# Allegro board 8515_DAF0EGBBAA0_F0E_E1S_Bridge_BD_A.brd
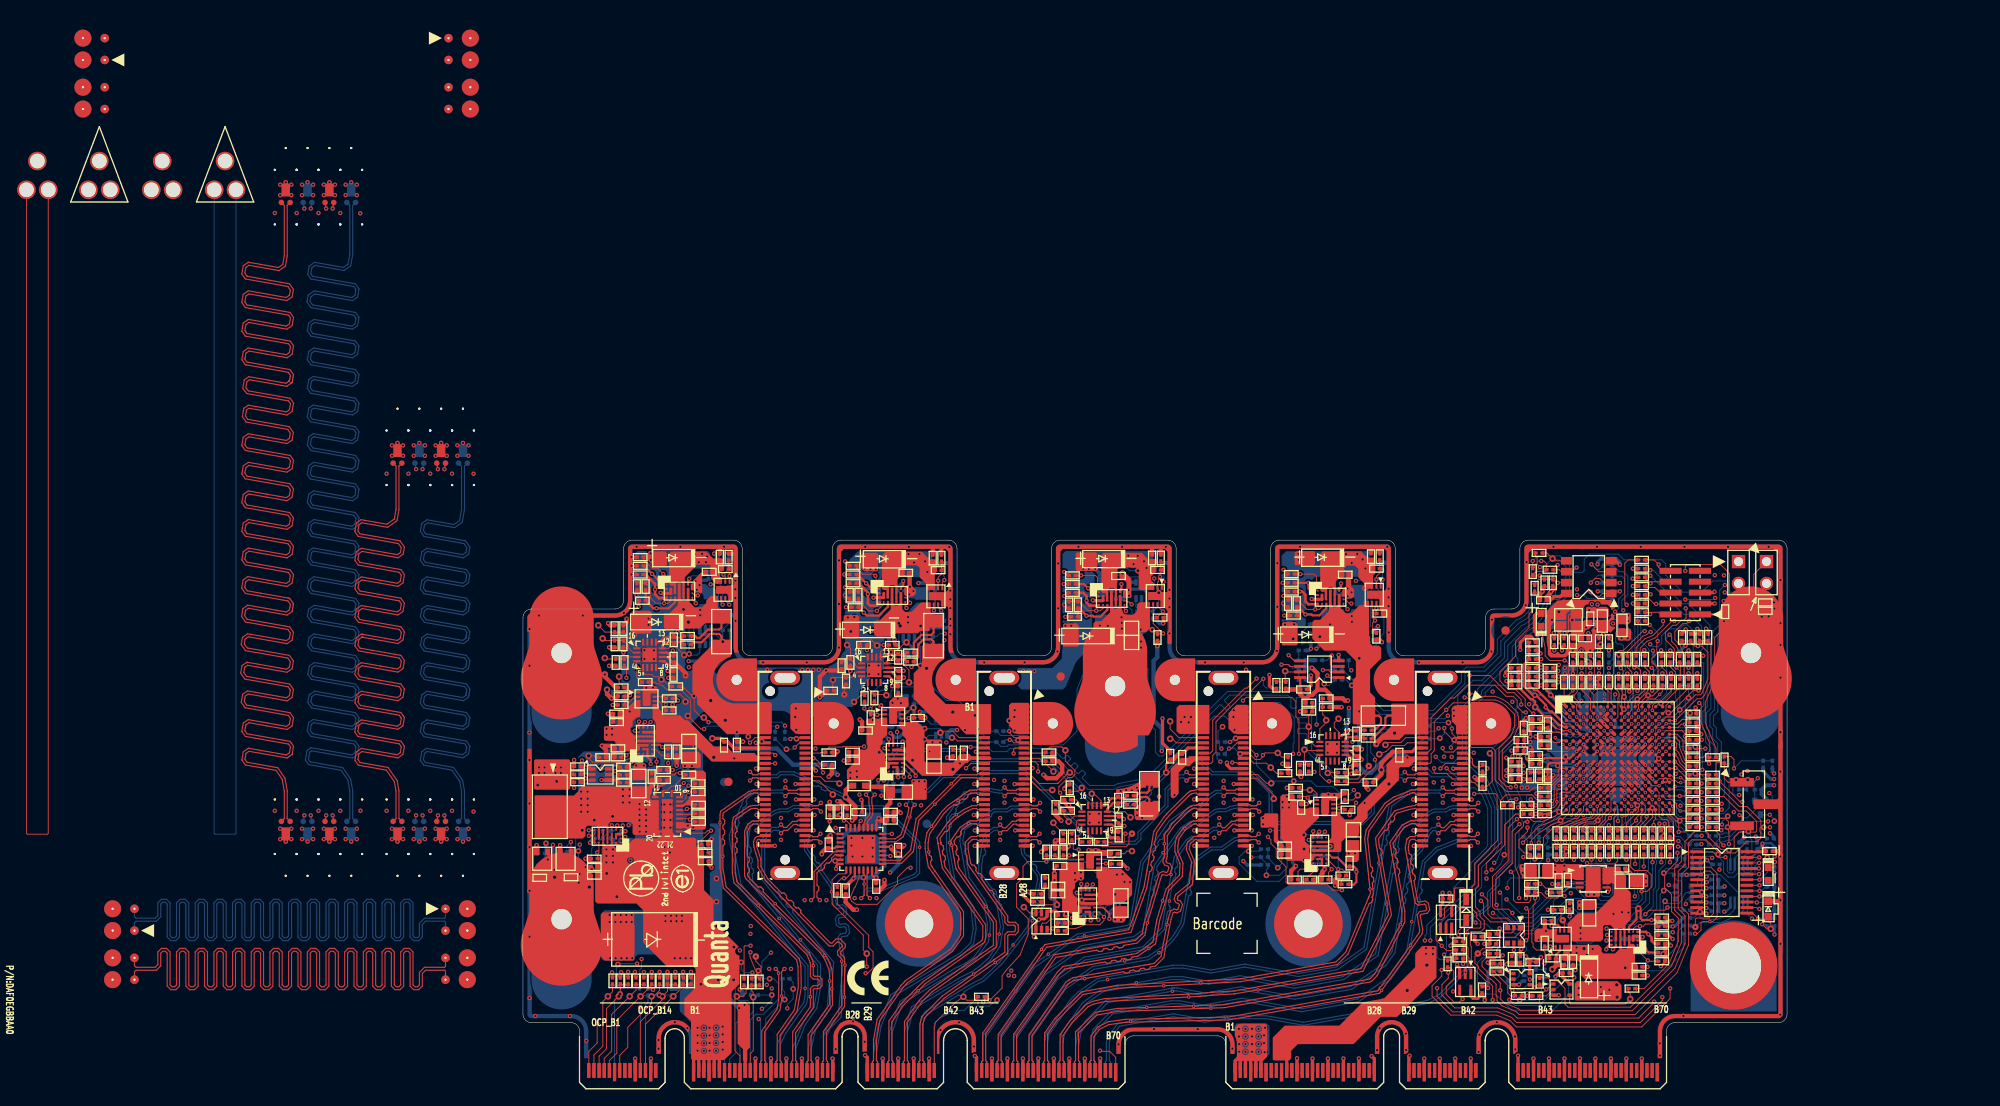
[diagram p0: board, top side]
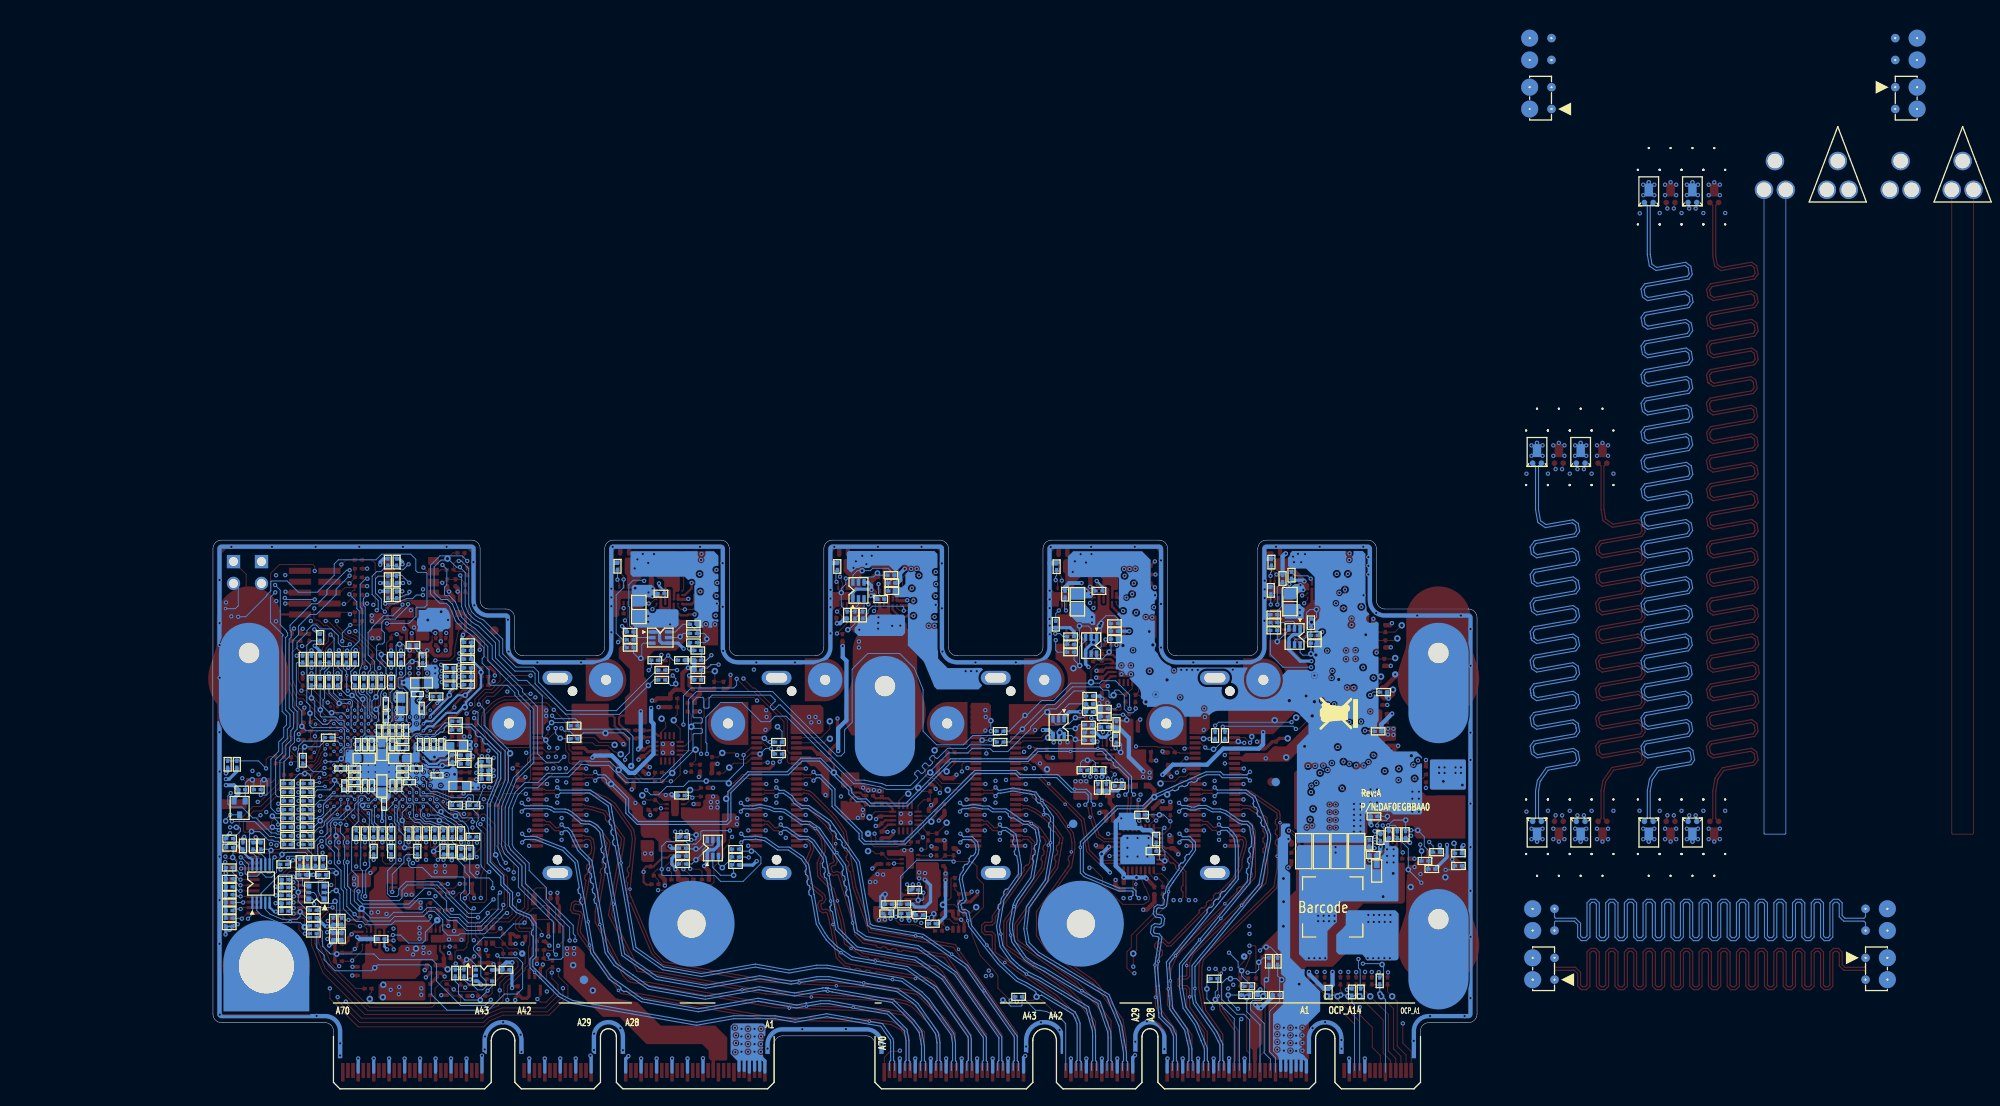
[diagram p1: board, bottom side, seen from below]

Outline 147.1 x 63.9 mm; copper layers: TOP, GND, IN1, GND1, VCC, VCC1, GND2, IN2, GND3, BOTTOM. Coordinates in mm from the lower left corner of the outline.
Outline path: 0,54.88 0,8.71 arc(0.29,8) 1,7.71 5.59,7.71 arc(6.3,7.42) 6.59,6.71 6.59,0.75 7.34,0 15.8,0 16.55,0.75 16.55,5.88 arc(17.68,7) 18.8,5.88 18.8,0.75 19.55,0 36.4,0 37.15,0.75 37.15,6.07 arc(38.08,7) 39,6.07 39,0.75 39.75,0 48.21,0 48.96,0.75 48.96,5.63 arc(50.34,7) 51.71,5.63 51.71,0.75 52.46,0 69.32,0 70.07,0.75 70.07,5.17 arc(70.36,5.88) 71.07,6.17 80.8,6.17 arc(81.51,5.88) 81.8,5.17 81.8,0.75 82.55,0 99.4,0 100.15,0.75 100.15,6.07 arc(101.08,7) 102,6.07 102,0.75 102.75,0 111.21,0 111.96,0.75 111.96,5.63 arc(113.34,7) 114.72,5.63 114.72,0.75 115.47,0 132.32,0 133.07,0.75 133.07,6.71 arc(133.36,7.42) 134.07,7.71 146.1,7.71 arc(146.81,8) 147.1,8.71 147.1,62.9 arc(146.81,63.61) 146.1,63.9 117.01,63.9 arc(116.3,63.61) 116.01,62.9 116.01,56.88 arc(115.72,56.17) 115.01,55.88 113.01,55.88 arc(112.3,55.59) 112.01,54.88 112.01,51.44 arc(111.72,50.73) 111.01,50.44 102.51,50.44 arc(101.8,50.73) 101.51,51.44 101.51,62.9 arc(101.22,63.61) 100.51,63.9 88.01,63.9 arc(87.3,63.61) 87.01,62.9 87.01,51.44 arc(86.72,50.73) 86.01,50.44 77.01,50.44 arc(76.3,50.73) 76.01,51.44 76.01,62.9 arc(75.72,63.61) 75.01,63.9 62.51,63.9 arc(61.8,63.61) 61.51,62.9 61.51,51.44 arc(61.22,50.73) 60.51,50.44 51.51,50.44 arc(50.8,50.73) 50.51,51.44 50.51,62.9 arc(50.22,63.61) 49.51,63.9 37.01,63.9 arc(36.3,63.61) 36.01,62.9 36.01,51.44 arc(35.72,50.73) 35.01,50.44 26.51,50.44 arc(25.8,50.73) 25.51,51.44 25.51,62.9 arc(25.22,63.61) 24.51,63.9 12.71,63.9 arc(12,63.61) 11.71,62.9 11.71,56.88 arc(11.42,56.17) 10.71,55.88 1,55.88 arc(0.29,55.59) 0,54.88

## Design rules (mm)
constraint set DEFAULT: min track width 0.109
net group BIC_ADCVREFN0: nets BIC_ADCVREFN0 BIC_ADCVREFP0
net group BIC_ADCVREFN1: nets BIC_ADCVREFN1 BIC_ADCVREFP1
net group BMC_HARTBEAT_LED: nets BMC_HARTBEAT_LED BMC_HARTBEAT_LED_R
net group CLKBUF_E1S_0_OE_N: nets CLKBUF_E1S_0_OE_N CLKBUF_E1S_0_OE_R_N
net group CLKBUF_E1S_1_OE_N: nets CLKBUF_E1S_1_OE_N CLKBUF_E1S_1_OE_R_N
net group CLKBUF_E1S_2_OE_N: nets CLKBUF_E1S_2_OE_N CLKBUF_E1S_2_OE_R_N
net group CLKBUF_E1S_3_OE_N: nets CLKBUF_E1S_3_OE_N CLKBUF_E1S_3_OE_R_N
net group DELTA_L_85_5INCH_BOT_: nets DELTA_L_85_5INCH_BOT_DN DELTA_L_85_5INCH_BOT_DP
net group DELTA_L_85_5INCH_IN1_: nets DELTA_L_85_5INCH_IN1_DN DELTA_L_85_5INCH_IN1_DP
net group DELTA_L_85_5INCH_IN2_: nets DELTA_L_85_5INCH_IN2_DN DELTA_L_85_5INCH_IN2_DP
net group DELTA_L_85_5INCH_TOP_: nets DELTA_L_85_5INCH_TOP_DN DELTA_L_85_5INCH_TOP_DP
net group DELTA_L_85_10INCH_BOT_: nets DELTA_L_85_10INCH_BOT_DN DELTA_L_85_10INCH_BOT_DP
net group DELTA_L_85_10INCH_IN1_: nets DELTA_L_85_10INCH_IN1_DN DELTA_L_85_10INCH_IN1_DP
net group DELTA_L_85_10INCH_IN2_: nets DELTA_L_85_10INCH_IN2_DN DELTA_L_85_10INCH_IN2_DP
net group DELTA_L_85_10INCH_TOP_: nets DELTA_L_85_10INCH_TOP_DN DELTA_L_85_10INCH_TOP_DP
net group FM_CARD_TYPE: nets CARD_TYPE_R FM_CARD_TYPE
net group FM_CLKBUF_EN: nets FM_CLKBUF_EN FM_CLKBUF_R_EN
net group FM_FRU_WC_N_R: nets FM_FRU_WC_N FM_FRU_WC_N_R
net group FM_MB_SLOT_ID0: nets FM_MB_SLOT_ID0 SLOT_ID0_R
net group FM_MB_SLOT_ID1: nets FM_MB_SLOT_ID1 SLOT_ID1_R
net group FM_P3V3_E1S_0_EN_G: nets FM_P3V3_E1S_0_EN_G FM_P3V3_E1S_0_EN_R_G
net group FM_P3V3_E1S_1_EN_G: nets FM_P3V3_E1S_1_EN_G FM_P3V3_E1S_1_EN_R_G
net group FM_P3V3_E1S_2_EN_G: nets FM_P3V3_E1S_2_EN_G FM_P3V3_E1S_2_EN_R_G
net group FM_P3V3_E1S_3_EN_G: nets FM_P3V3_E1S_3_EN_G FM_P3V3_E1S_3_EN_R_G
net group FM_P12V_E1S_0_EN_G: nets FM_P12V_E1S_0_EN_G FM_P12V_E1S_0_EN_R_G
net group FM_P12V_E1S_1_EN_G: nets FM_P12V_E1S_1_EN_G FM_P12V_E1S_1_EN_R_G
net group FM_P12V_E1S_2_EN_G: nets FM_P12V_E1S_2_EN_G FM_P12V_E1S_2_EN_R_G
net group FM_P12V_E1S_3_EN_G: nets FM_P12V_E1S_3_EN_G FM_P12V_E1S_3_EN_R_G
net group FM_P12V_EDGE_EN: nets FM_P12V_EDGE_EN FM_P12V_EDGE_EN_R
net group FM_P12V_EDGE_EN_G: nets FM_P12V_EDGE_EN_G FM_P12V_EDGE_EN_R_G
net group FM_POWER_EN: nets FM_POWER_EN FM_POWER_EN_R
net group FM_PRSNT_E1S_0_N: nets FM_PRSNT_E1S_0_N FM_PRSNT_E1S_0_R_N
net group FM_PRSNT_E1S_1_N: nets FM_PRSNT_E1S_1_N FM_PRSNT_E1S_1_R_N
net group FM_PRSNT_E1S_2_N: nets FM_PRSNT_E1S_2_N FM_PRSNT_E1S_2_R_N
net group FM_PRSNT_E1S_3_N: nets FM_PRSNT_E1S_3_N FM_PRSNT_E1S_3_R_N
net group FM_PWRDIS_E1S_0: nets FM_PWRDIS_E1S_0 FM_PWRDIS_E1S_R_0
net group FM_PWRDIS_E1S_1: nets FM_PWRDIS_E1S_1 FM_PWRDIS_E1S_R_1
net group FM_PWRDIS_E1S_2: nets FM_PWRDIS_E1S_2 FM_PWRDIS_E1S_R_2
net group FM_PWRDIS_E1S_3: nets FM_PWRDIS_E1S_3 FM_PWRDIS_E1S_R_3
net group IRQ_P3V3_EDGE_FLT_N: nets IRQ_P3V3_EDGE_FLT_N P3V3_EDGE_OCP_FLT_N
net group IRQ_P12V_EDGE_FLT_N: nets IRQ_P12V_EDGE_FLT_N IRQ_P12V_EDGE_FLT_N_R
net group IRQ_SMB_ALERT_N: nets IRQ_SMB_ALERT_N IRQ_SMB_ALERT_R_N
net group IRQ_TMP75_ALERT_N: nets IRQ_TMP75_ALERT_N TMP75_ALERT_N_R
net group JTAG_BIC_DEBUG_R_TDO: nets JTAG_BIC_DEBUG_R_TDO JTAG_BIC_DEBUG_TDO
net group LED_BIC_E1S_0: nets LED_BIC_E1S_0 LED_BIC_E1S_R_0
net group LED_BIC_E1S_1: nets LED_BIC_E1S_1 LED_BIC_E1S_R_1
net group LED_BIC_E1S_2: nets LED_BIC_E1S_2 LED_BIC_E1S_R_2
net group LED_BIC_E1S_3: nets LED_BIC_E1S_3 LED_BIC_E1S_R_3
net group LED_PWRGD_P12V_E1S_ALL: nets LED_PWRGD_P12V_E1S_ALL LED_PWRGD_P12V_E1S_ALL_R
net group P1V2_VDD_PG_R: nets P1V2_VDD_PG_R PWRGD_P1V2_STBY_R
net group P3V3_EDGE_OV: nets P3V3_EDGE_OV P3V3_EDGE_UV
net group P12V_AUX_HSC_PWRGD: nets P12V_AUX_HSC_PWRGD PWRGD_P12V_AUX
net group PU_DB800_HI_BW: nets PU_DB800_HI_BW PU_DB800_HI_BW_R
net group PWRGD_EXP_PWROK: nets PWRGD_EXP_PWROK PWRGD_EXP_PWROK_R
net group RST_BIC_E1S_0_N: nets RST_BIC_E1S_0_N RST_BIC_E1S_0_R_N
net group RST_BIC_E1S_1_N: nets RST_BIC_E1S_1_N RST_BIC_E1S_1_R_N
net group RST_BIC_E1S_2_N: nets RST_BIC_E1S_2_N RST_BIC_E1S_2_R_N
net group RST_BIC_E1S_3_N: nets RST_BIC_E1S_3_N RST_BIC_E1S_3_R_N
net group RST_MB_N: nets RST_MB_N RST_MB_R_N
net group RST_SMB_E1S_0_N: nets RST_SMB_E1S_0_N RST_SMB_E1S_0_R_N
net group RST_SMB_E1S_1_N: nets RST_SMB_E1S_1_N RST_SMB_E1S_1_R_N
net group RST_SMB_E1S_2_N: nets RST_SMB_E1S_2_N RST_SMB_E1S_2_R_N
net group RST_SMB_E1S_3_N: nets RST_SMB_E1S_3_N RST_SMB_E1S_3_R_N
net group SMB_BMC_CPLD_SCL: nets SMB_BMC_CPLD_SCL SMB_BMC_CPLD_SCL_R
net group SMB_BMC_CPLD_SDA: nets SMB_BMC_CPLD_SDA SMB_BMC_CPLD_SDA_R
net group SMB_IPMB_3V3SB_SCL: nets SMB_IPMB_3V3SB_SCL SMB_IPMB_3V3SB_SCL_R
net group SMB_IPMB_3V3SB_SDA: nets SMB_IPMB_3V3SB_SDA SMB_IPMB_3V3SB_SDA_R
net group TDR_DIFF_85_BOT_D: nets TDR_DIFF_85_BOT_DN TDR_DIFF_85_BOT_DP
net group TDR_DIFF_85_IN1_D: nets TDR_DIFF_85_IN1_DN TDR_DIFF_85_IN1_DP
net group TDR_DIFF_85_IN2_D: nets TDR_DIFF_85_IN2_DN TDR_DIFF_85_IN2_DP
net group TDR_DIFF_85_TOP_D: nets TDR_DIFF_85_TOP_DN TDR_DIFF_85_TOP_DP
net group TP_CLK_100M_E1S_0_D: nets TP_CLK_100M_E1S_0_DN TP_CLK_100M_E1S_0_DP
net group TP_CLK_100M_E1S_1_D: nets TP_CLK_100M_E1S_1_DN TP_CLK_100M_E1S_1_DP
net group TP_CLK_100M_E1S_2_D: nets TP_CLK_100M_E1S_2_DN TP_CLK_100M_E1S_2_DP
net group TP_CLK_100M_E1S_3_D: nets TP_CLK_100M_E1S_3_DN TP_CLK_100M_E1S_3_DP
net group BIC_EXTRST_N: nets BIC_EXTRST_N BIC_EXTRST_N_IO_EXP BIC_EXTRST_N_IO_EXP_R BIC_EXTRST_N_R RST_BIC_EXTRST_N
net group BIC_FWSPICK: nets BIC_FWSPICK BIC_FWSPICK_IO_EXP BIC_MB_FWSPICK
net group BIC_SRST_N: nets BIC_SRST_N BIC_SRST_N_IO_EXP BIC_SRST_N_IO_EXP_R BIC_SRST_N_R JTAG_BIC_SRST_N RST_BIC_SRST_N
net group CLK_25M_OSC_BIC_CLKIN: nets CLK_25M_OSC_BIC_CLKIN
net group FM_AUX_PWR_RST_EN: nets FM_AUX_PWR_EN FM_AUX_PWR_EN_R FM_AUX_PWR_RST_EN P1V2_STBY_EN_R
net group IRQ_INA230_E1S_0_ALERT_N: nets INA230_E1S_0_ALERT_R_N IRQ_INA230_E1S_0_ALERT_N IRQ_INA230_E1S_0_ALERT_R_N
net group IRQ_INA230_E1S_1_ALERT_N: nets INA230_E1S_1_ALERT_R_N IRQ_INA230_E1S_1_ALERT_N IRQ_INA230_E1S_1_ALERT_R_N
net group IRQ_INA230_E1S_2_ALERT_N: nets INA230_E1S_2_ALERT_R_N IRQ_INA230_E1S_2_ALERT_N IRQ_INA230_E1S_2_ALERT_R_N
net group IRQ_INA230_E1S_3_ALERT_N: nets INA230_E1S_3_ALERT_R_N IRQ_INA230_E1S_3_ALERT_N IRQ_INA230_E1S_3_ALERT_R_N
net group JTAG_BIC_DEBUG_TCK: nets JTAG_BIC_DEBUG_TCK
net group JTAG_BIC_DEBUG_TDI: nets JTAG_BIC_DEBUG_TDI
net group JTAG_BIC_DEBUG_TMS: nets JTAG_BIC_DEBUG_TMS
net group P1V2_RST_PG_EN: nets P1V2_RST_PG P1V2_RST_PG_EN P1V2_RST_PG_R
net group P3V3_E1S_0_OV: nets FM_P3V3_E1S_0_EN FM_P3V3_E1S_0_EN_D FM_P3V3_E1S_0_R_EN FM_P3V3_E1S_0_SW_EN P3V3_E1S_0_OV
net group P3V3_E1S_1_OV: nets FM_P3V3_E1S_1_EN FM_P3V3_E1S_1_EN_D FM_P3V3_E1S_1_R_EN FM_P3V3_E1S_1_SW_EN P3V3_E1S_1_OV
net group P3V3_E1S_2_OV: nets FM_P3V3_E1S_2_EN FM_P3V3_E1S_2_EN_D FM_P3V3_E1S_2_R_EN FM_P3V3_E1S_2_SW_EN P3V3_E1S_2_OV
net group P3V3_E1S_3_OV: nets FM_P3V3_E1S_3_EN FM_P3V3_E1S_3_EN_D FM_P3V3_E1S_3_R_EN FM_P3V3_E1S_3_SW_EN P3V3_E1S_3_OV
net group P12V_AUX_EN_MP5022: nets FM_P12V_EDGE_EN_D P12V_AUX_EN_MP5022 P12V_AUX_OV P12V_AUX_UV
net group P12V_E1S_0_IN_N: nets P12V_E1S_0_IN_N P12V_E1S_0_IN_P P12V_E1S_0_IN_SENN P12V_E1S_0_IN_SENP
net group P12V_E1S_0_OV: nets FM_P12V_E1S_0_EN FM_P12V_E1S_0_EN_D FM_P12V_E1S_0_R_EN FM_P12V_E1S_0_SW_EN P12V_E1S_0_OV
net group P12V_E1S_1_IN_N: nets P12V_E1S_1_IN_N P12V_E1S_1_IN_P P12V_E1S_1_IN_SENN P12V_E1S_1_IN_SENP
net group P12V_E1S_1_OV: nets FM_P12V_E1S_1_EN FM_P12V_E1S_1_EN_D FM_P12V_E1S_1_R_EN FM_P12V_E1S_1_SW_EN P12V_E1S_1_OV
net group P12V_E1S_2_IN_N: nets P12V_E1S_2_IN_N P12V_E1S_2_IN_P P12V_E1S_2_IN_SENN P12V_E1S_2_IN_SENP
net group P12V_E1S_2_OV: nets FM_P12V_E1S_2_EN FM_P12V_E1S_2_EN_D FM_P12V_E1S_2_R_EN FM_P12V_E1S_2_SW_EN P12V_E1S_2_OV
net group P12V_E1S_3_IN_N: nets P12V_E1S_3_IN_N P12V_E1S_3_IN_P P12V_E1S_3_IN_SENN P12V_E1S_3_IN_SENP
net group P12V_E1S_3_OV: nets FM_P12V_E1S_3_EN FM_P12V_E1S_3_EN_D FM_P12V_E1S_3_R_EN FM_P12V_E1S_3_SW_EN P12V_E1S_3_OV
net group PRSNTB0_N: nets PRSNTA1_N PRSNTB0_N PRSNTB1_N PRSNTB2_N PRSNTB3_N
net group RESET_R_EXTRST_N: nets RESET_R_EXTRST_N RESET_R_N RESET_R_SRST_N SELECT_RST_N SELECT_RST_R_N
net group SMB_CLKBUF_SCL_R: nets SMB_BIC_SENSOR_R_SCL SMB_CLKBUF_SCL_R SMB_FRU_SCL_R SMB_SENSOR_SCL SMB_TMP75_SCL_R
net group SMB_E1S_0_SDA: nets SMB_BIC_E1S_0_R_SDA SMB_E1S_0_R_SDA SMB_E1S_0_SDA SMB_INA230_E1S_0_SDA
net group SMB_E1S_1_SDA: nets SMB_BIC_E1S_1_R_SDA SMB_E1S_1_R_SDA SMB_E1S_1_SDA SMB_INA230_E1S_1_SDA
net group SMB_E1S_2_SDA: nets SMB_BIC_E1S_2_R_SDA SMB_E1S_2_R_SDA SMB_E1S_2_SDA SMB_INA230_E1S_2_SDA
net group SMB_E1S_3_SDA: nets SMB_BIC_E1S_3_R_SDA SMB_E1S_3_R_SDA SMB_E1S_3_SDA SMB_INA230_E1S_3_SDA
net group SMB_INA230_E1S_0_SCL: nets SMB_BIC_E1S_0_R_SCL SMB_E1S_0_R_SCL SMB_E1S_0_SCL SMB_INA230_E1S_0_SCL
net group SMB_INA230_E1S_1_SCL: nets SMB_BIC_E1S_1_R_SCL SMB_E1S_1_R_SCL SMB_E1S_1_SCL SMB_INA230_E1S_1_SCL
net group SMB_INA230_E1S_2_SCL: nets SMB_BIC_E1S_2_R_SCL SMB_E1S_2_R_SCL SMB_E1S_2_SCL SMB_INA230_E1S_2_SCL
net group SMB_INA230_E1S_3_SCL: nets SMB_BIC_E1S_3_R_SCL SMB_E1S_3_R_SCL SMB_E1S_3_SCL SMB_INA230_E1S_3_SCL
net group SMB_IO_EXP_SCL: nets SMB_IO_EXP_SCL SMB_MB_CPLD_BIC_SCL SMB_MB_CPLD_SCL SMB_MB_CPLD_SCL_R
net group SMB_IO_EXP_SDA: nets SMB_IO_EXP_SDA SMB_MB_CPLD_BIC_SDA SMB_MB_CPLD_SDA SMB_MB_CPLD_SDA_R
net group SMB_IPMB_3V3AUX_SCL: nets SMB_IPMB_3V3AUX_SCL SMB_IPMB_AUX_SCL_R SMB_MBBIC_BIC_R_SCL
net group SMB_IPMB_3V3AUX_SDA: nets SMB_IPMB_3V3AUX_SDA SMB_IPMB_AUX_SDA_R SMB_MBBIC_BIC_R_SDA
net group SMB_SENSOR_SDA: nets SMB_BIC_SENSOR_R_SDA SMB_CLKBUF_SDA_R SMB_FRU_SDA_R SMB_SENSOR_SDA SMB_TMP75_SDA_R
net group UART_BIC5_R_RXD: nets UART_BIC5_R_RXD UART_HOST_TXD UART_MB_TX UART_MB_TX_R
net group UART_BIC5_R_TXD: nets UART_BIC5_R_TXD UART_HOST_RXD UART_MB_RX

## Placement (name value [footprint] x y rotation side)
C48  0.047UF  [C0402-0201]  23.93 61.34 90 bottom
C49  0.047UF  [C0402-0201]  48.92 60.81 90 bottom
C50  0.1UF  [C0402-0201]  22.91 61.93 90 top
C51  10UF  [C0805_H61]  21.77 56.74 90 bottom
C52  0.1UF  [C0402-0201]  47.68 61.8 90 top
C53  10UF  [C0805_H61]  46.5 56.73 90 bottom
C54  0.047UF  [C0402-0201]  74.45 60.83 90 bottom
C55  0.047UF  [C0402-0201]  100.03 60.86 90 bottom
C56  0.1UF  [C0402-0201]  73.2 61.82 90 top
C57  10UF  [C0805_H61]  70.82 52.81 270 top
C58  0.1UF  [C0402-0201]  98.68 61.98 90 top
C59  10UF  [C0805_H61]  97.54 55.83 90 bottom
C60  100NF  [C0402-0201]  11.43 46.74 180 top
C61  100NF  [C0402-0201]  43.36 44.25 0 bottom
C62  0.1UF  [C0402-0201]  10.9 43.69 180 top
C63  0.1UF  [C0402-0201]  39.86 41.73 180 top
C64  10UF  [C0805_H61]  19.3 39.62 270 top
C65  10UF  [C0805_H61]  47.83 38.4 90 top
C66  100NF  [C0402-0201]  89.92 35.05 180 top
C67  100NF  [C0402-0201]  62.89 27.58 90 top
C68  0.1UF  [C0402-0201]  90.55 32.77 90 top
C69  0.1UF  [C0402-0201]  62.5 25.95 180 top
C70  10UF  [C0805_H61]  96.65 29.34 270 top
C71  10UF  [C0805_H61]  69.57 21.64 270 top
C72  0.1UF  [C0402-0201]  17.53 48.26 270 top
C73  0.1UF  [C0402-0201]  17.53 50.04 270 top
C74  0.1UF  [C0402-0201]  17.55 52.3 270 top
C75  0.1UF  [C0402-0201]  43.66 46.51 270 top
C76  0.1UF  [C0402-0201]  43.66 48.29 270 top
C77  0.1UF  [C0402-0201]  43.66 50.27 270 top
C78  0.1UF  [C0402-0201]  69.32 29.54 270 top
C79  0.1UF  [C0402-0201]  69.32 31.32 270 top
C80  0.1UF  [C0402-0201]  69.27 33.6 270 top
C81  0.1UF  [C0402-0201]  97 37.36 270 top
C82  0.1UF  [C0402-0201]  97 39.14 270 top
C83  0.1UF  [C0402-0201]  96.98 41.33 270 top
C84  0.1UF  [C0402-0201]  118.75 56.9 0 top
C85  0.1UF  [C0402-0201]  90.83 46.51 0 top
C86  0.1UF  [C0402-0201]  122.2 14.81 90 top
C87  0.1UF  [C0402-0201]  118.9 16.97 270 top
C88  10UF  [C0805_H57]  124.08 20.5 90 top
C89  1000PF  [C0402-0201]  133.12 17.75 270 bottom
C90  1000PF  [C0402-0201]  132.11 17.75 270 bottom
C91  1000PF  [C0402-0201]  111.15 17.73 180 top
C92  1000PF  [C0402-0201]  116.07 15.07 90 top
C96  1UF  [C0402-0201]  13.64 59.89 0 top
C102  1UF  [C0402-0201]  38.4 58.88 0 top
C105  1UF  [C0402-0201]  63.93 57.76 0 top
C108  1UF  [C0402-0201]  89.41 57.91 0 top
C109  4700PF  [C0402-0201]  21.59 59.82 270 bottom
C110  4700PF  [C0402-0201]  43.99 57.99 0 bottom
C111  4700PF  [C0402-0201]  69.39 57.02 0 bottom
C112  4700PF  [C0402-0201]  94.97 57.66 0 bottom
C113  1UF  [C0402-0201]  11.06 39.65 0 top
C115  0.01UF  [C0402-0201]  11.51 41.63 180 bottom
C116  1UF  [C0402-0201]  38.35 38.23 0 top
C118  0.01UF  [C0402-0201]  41.99 40.72 90 bottom
C119  1UF  [C0402-0201]  62.26 22.66 0 top
C121  0.01UF  [C0402-0201]  65.43 23.16 0 bottom
C122  1UF  [C0402-0201]  88.64 27.27 0 top
C124  0.01UF  [C0402-0201]  92.43 29.31 0 bottom
C125  1UF  [C0402-0201]  129.86 14.21 180 top
C127  0.01UF  [C0402-0201]  127.53 17.45 0 bottom
C128  1UF  [C0402-0201]  16.36 37.13 180 top
C129  1UF  [C0402-0201]  44.12 35.1 90 bottom
C130  1UF  [C0402-0201]  66.6 20.42 0 bottom
C131  1UF  [C0402-0201]  93.34 24.36 0 top
C132  1UF  [C0402-0201]  132.51 16.89 180 top
C147  10UF  [C0402-0201]  42.77 32.25 0 top
C148  0.1UF  [C0402-0201]  42.77 31.24 0 top
C149  0.1UF  [C0402-0201]  37.56 23.06 270 top
C150  0.1UF  [C0402-0201]  41.11 23.57 270 top
C157  10UF  [C0402-0201]  39.08 32.23 0 top
C158  0.1UF  [C0402-0201]  43.64 27.79 90 top
C159  0.1UF  [C0402-0201]  35.57 28.42 90 top
C160  1UF  [C0402-0201]  21.67 60.21 180 top
C161  1UF  [C0402-0201]  44.54 60.09 0 top
C162  1UF  [C0402-0201]  69.3 59.73 0 top
C163  1UF  [C0402-0201]  95.68 59.88 0 top
C164  1UF  [C0402-0201]  10.89 42.71 0 top
C165  1UF  [C0402-0201]  38.35 39.26 0 top
C166  1UF  [C0402-0201]  62.26 23.65 0 top
C167  1UF  [C0402-0201]  88.64 28.32 0 top
C168  1UF  [C0402-0201]  129.87 13.19 180 top
C169  1UF  [C0402-0201]  8.3 25.83 180 top
C170  1UF  [C0402-0201]  11.99 31.73 180 bottom
C171  4700PF  [C0402-0201]  8.29 26.8 180 top
C172  10UF  [C0805_H61]  13.46 35.56 90 top
C176  1UF  [C0402-0201]  21.21 26.52 0 top
C177  0.047UF  [C0402-0201]  20.44 33.08 0 top
C178  0.01UF  [C0402-0201]  20.39 35.58 180 top
C179  0.22UF  [C0402-0201]  20.44 31.1 180 top
C180  1UF  [C0402-0201]  12.1 27.23 0 bottom
C202  0.01UF  [C0402-0201]  117.86 43.05 180 top
C203  0.01UF  [C0402-0201]  119.25 42.42 270 top
C204  0.01UF  [C0402-0201]  117.86 42.04 180 top
C205  0.01UF  [C0402-0201]  117.86 37.85 180 bottom
C206  0.01UF  [C0402-0201]  119.25 38.48 90 bottom
C207  0.01UF  [C0402-0201]  117.86 38.86 180 bottom
C208  0.1UF  [C0402_OCTAGONXA]  129.43 40.09 270 bottom
C209  0.22UF  [C0402_OCTAGONXA]  125 39.7 0 bottom
C210  0.1UF  [C0402_OCTAGONXA]  126.21 41.7 90 bottom
C211  0.1UF  [C0402_OCTAGONXA]  125.41 35.31 90 bottom
C212  0.1UF  [C0402_OCTAGONXA]  130.63 35.71 180 bottom
C213  0.1UF  [C0402_OCTAGONXA]  127.02 41.7 90 bottom
C214  0.1UF  [C0402_OCTAGONXA]  126.21 35.31 90 bottom
C215  0.1UF  [C0402_OCTAGONXA]  127.79 41.7 90 bottom
C216  1UF  [C0402_OCTAGONXA]  125.03 36.51 0 bottom
C217  1UF  [C0402_OCTAGONXA]  130.63 36.51 180 bottom
C218  1UF  [C0402_OCTAGONXA]  131.81 35.3 270 bottom
C219  22UF  [C0603]  125.36 38.47 0 bottom
C220  0.1UF  [C0402_OCTAGONXA]  125.02 40.5 0 bottom
C221  0.1UF  [C0402_OCTAGONXA]  126.23 40.09 270 bottom
C222  0.1UF  [C0402_OCTAGONXA]  128.63 40.09 270 bottom
C223  1UF  [C0402_OCTAGONXA]  128.61 35.31 90 bottom
C224  1UF  [C0402_OCTAGONXA]  130.63 37.31 180 bottom
C225  22UF  [C0603]  127.44 35.27 90 bottom
C226  22UF  [C0603]  127.44 39.54 270 bottom
C227  22UF  [C0603]  129.5 38.47 180 bottom
C228  0.1UF  [C0402_OCTAGONXA]  122.22 40.1 90 bottom
C229  1UF  [C0402_OCTAGONXA]  121.42 40.1 90 bottom
C230  1UF  [C0402_OCTAGONXA]  120.52 40.1 90 bottom
C231  1UF  [C0402_OCTAGONXA]  123.02 40.1 90 bottom
C232  1UF  [C0402_OCTAGONXA]  126.99 43.31 270 bottom
C233  0.1UF  [C0402_OCTAGONXA]  129.4 35.31 90 bottom
C234  1UF  [C0402_OCTAGONXA]  130.23 40.09 270 bottom
C235  2.2UF  [C0402-0201]  123.83 51.69 0 bottom
C236  0.1UF  [C0402-0201]  122.17 52.07 270 top
C237  22UF  [C0603]  125.6 54.48 270 top
C239  1UF  [C0402_OCTAGONXA]  125.03 37.31 0 bottom
C240  0.1UF  [C0402_OCTAGONXA]  123.43 37.31 180 bottom
C243  0.1UF  [C0402_OCTAGONXA]  122.81 44.32 90 bottom
C244  4.7UF  [C0402_OCTAGONXA]  123.32 45.97 180 bottom
C246  0.1UF  [C0402_OCTAGONXA]  125.41 41.7 90 bottom
C247  4.7UF  [C0402_OCTAGONXA]  124.62 41.7 90 bottom
C249  22UF  [C0805_H61]  118.24 25.4 180 top
C250  0.1UF  [C0402-0201]  120.52 24.26 270 top
C251  10UF  [C0805_H61]  128.75 24.17 0 top
C252  0.001UF  [C0402]  117.35 22.86 180 top
C284  0.1UF  [C0402-0201]  115.44 46.99 0 top
C285  0.1UF  [C0402-0201]  117.47 50.04 180 top
C286  0.1UF  [C0402-0201]  117.47 50.04 180 bottom
C287  0.1UF  [C0402-0201]  119.25 36.45 90 top
C288  0.1UF  [C0402-0201]  115.44 36.07 0 bottom
C289  0.1UF  [C0402-0201]  115.44 36.07 0 top
C290  0.1UF  [C0402-0201]  116.08 39.4 0 top
C291  0.1UF  [C0402-0201]  119.51 46.99 180 top
C292  0.1UF  [C0402-0201]  117.47 47.07 180 top
C293  0.1UF  [C0402-0201]  117.47 47.07 180 bottom
C294  0.1UF  [C0402-0201]  119.51 46.99 180 bottom
C295  0.1UF  [C0402-0201]  143.61 28.29 90 bottom
C296  0.1UF  [C0402-0201]  117.86 37.85 0 top
C297  0.1UF  [C0402_OCTAGONXA]  132.23 37.31 0 bottom
C298  0.1UF  [C0402_OCTAGONXA]  130.63 34.91 180 bottom
C299  0.1UF  [C0402-0201]  139.91 55.57 90 top
C300  0.1UF  [C0402_OCTAGONXA]  126.98 44.88 90 bottom
C301  0.1UF  [C0402_OCTAGONXA]  127.18 33.13 270 bottom
C302  0.1UF  [C0402-0201]  4.7 27.56 180 bottom
C303  0.1UF  [C0402-0201]  2.16 27.43 180 bottom
C304  0.1UF  [C0402-0201]  143.74 34.84 0 bottom
C306  0.1UF  [C0402-0201]  117.5 14.73 0 top
C307  0.1UF  [C0402-0201]  121.39 13.49 0 top
C308  0.1UF  [C0402-0201]  107.42 22.15 0 top
C309  0.1UF  [C0402-0201]  113 13.87 180 bottom
C310  1UF  [C0402-0201]  108.99 17.17 0 top
C311  0.1UF  [C0402-0201]  111.61 11.53 90 top
C312  0.1UF  [C0402_OCTAGONXA]  121.03 36.51 180 bottom
C313  0.1UF  [C0402_OCTAGONXA]  124.23 35.71 0 bottom
C314  0.1UF  [C0402-0201]  145.04 27.68 0 top
C315  0.1UF  [C0402-0201]  18.92 52.81 180 bottom
C316  0.1UF  [C0402-0201]  42.19 53.29 180 bottom
C317  0.1UF  [C0402-0201]  68.1 58.9 180 bottom
C318  0.1UF  [C0402-0201]  91.19 51.97 0 bottom
C319  0.1UF  [C0402-0201]  11.68 35.66 180 top
C320  0.1UF  [C0402-0201]  45.21 41.49 180 bottom
C321  0.1UF  [C0402-0201]  59.87 21.79 180 top
C322  0.1UF  [C0402-0201]  92.46 27.1 0 bottom
D2  SMF14A  [SOD123F]  17.35 61.8 0 top
D3  SMF14A  [SOD123F]  41.86 61.67 0 top
D4  SS1040  [SOD123_2-65X1-6]  15.37 54.36 0 top
D5  SS1040  [SOD123_2-65X1-6]  40.03 53.44 0 top
D6  SMF14A  [SOD123F]  67.39 61.7 0 top
D7  SMF14A  [SOD123F]  92.86 61.85 0 top
D8  SS1040  [SOD123_2-65X1-6]  65.56 52.73 0 top
D9  SS1040  [SOD123_2-65X1-6]  91.03 52.88 0 top
D10  LED BLUE  [LED_LTSTS270KSKT]  144.91 20.95 90 top
D11  LED_GREEN  [LED_19217_H22]  144.91 25.02 90 top
D21  SMF14A  [SOD123F]  124.05 12.85 90 top
D22  SBR15U30SP5-13  [POWERDI5XA]  3.13 32.84 270 top
D23  SMCJ13A-13-F-01  [D_SMCJ170]  15.11 17.4 0 top
D24  LED_GREEN  [LED_19217_H22]  118.49 54.61 270 top
D25  SDMK0340L-7-F  [SOD323XB]  109.75 20.85 90 top
DM4  -  [PB-E1_SMALL]  13.76 24.5 90 top
DM5  -  [WEEE]  13.84 42.04 90 bottom
DM6  CE_LOGO_4.8X4  [CE_5X4]  37.71 10.88 0 top
GF1  FCONN168_6-2340321-2  [GOLD_168P_6-2340321-2]  38.06 6.08 0 top
GF2  FCONN140_6-2340324-2  [GOLD_140P_6-2340324-2]  101.08 6.08 0 top
H3  -  [HOLE_C10-2D6-4B10_R5-6X10B_NPB]  140.88 14.31 0 top
H4  -  [HOLE_C7-5D3_5B7_OB7XC4-75TC3-5B_NPM_SPD]  4.49 50.76 0 top
H5  -  [HOLE_C8D3-3B10_NPM]  91.4 19.23 0 top
H6  -  [HOLE_C5D2B4_R2-23X5T_NPM]  24.86 47.63 90 top
H7  -  [HOLE_C7-5D3_5B7_OB7XC4-75TC3-5B_NPM_SPD]  4.49 19.76 0 top
H8  -  [HOLE_C7-5D3_5B7_OB7XC4-75TC3-5B_NPM_SPD]  68.9 46.9 0 top
H9  -  [HOLE_C7-5D3_5B7_OB7XC4-75TC3-5B_NPM_SPD]  142.9 50.76 0 top
H10  -  [HOLE_C8D3-3B10_NPM]  46.1 19.23 0 top
H11  -  [HOLE_C5D2B4_R2-23X5T_NPM]  36.16 42.55 270 top
H12  -  [HOLE_C5D2B4_R2-23X5T_NPM]  50.36 47.63 90 top
H13  -  [HOLE_C5D2B4_R2-23X5T_NPM]  61.66 42.55 270 top
H14  -  [HOLE_C5D2B4_R2-23X5T_NPM]  75.86 47.63 90 top
H15  -  [HOLE_C5D2B4_R2-23X5T_NPM]  87.16 42.55 270 top
H16  -  [HOLE_C5D2B4_R2-23X5T_NPM]  101.36 47.63 90 top
H17  -  [HOLE_C5D2B4_R2-23X5T_NPM]  112.66 42.55 270 top
J1  SCONN3_212-H91-03GBR1  [HEADER1X3SXE_H367]  143.23 33.16 0 top
J2  SCONN10_232-H97-05GBR1  [HEADER2X5SXM]  135.25 57.78 180 top
J4  SCONN56_1-2327679-3  [CON_F56S2H4D_P0-6W4-6_LUHXA]  30.51 36.5 0 top
J5  SCONN56_1-2327679-3  [CON_F56S2H4D_P0-6W4-6_LUHXA]  56.01 36.5 0 top
J6  SCONN56_1-2327679-3  [CON_F56S2H4D_P0-6W4-6_LUHXA]  81.51 36.5 0 top
J7  SCONN56_1-2327679-3  [CON_F56S2H4D_P0-6W4-6_LUHXA]  107.01 36.5 0 top
J8  DELTA-L  [TRIANG_LAUNCH_3PXA]  -14.6 29.84 0 top
J9  DELTA-L  [TRIANG_LAUNCH_3PXA]  -14.61 74.17 180 top
J10  DELTA-L  [TRIANG_LAUNCH_3PXA]  -6.99 29.84 180 bottom
J11  DELTA-L  [TRIANG_LAUNCH_3PXA]  -6.98 74.17 0 bottom
J12  -  [TDR_3P_C85P67_141_100M_Q]  -41.98 108.05 0 bottom
J13  DELTA-L  [TRIANG_LAUNCH_3PXA]  -12.06 29.84 180 bottom
J14  DELTA-L  [TRIANG_LAUNCH_3PXA]  -12.06 74.17 0 bottom
J15  -  [TDR_3P_C85P67_141_100M_Q]  -34.66 108.05 180 top
J16  -  [TDR_3P_C85P67_141_100M_Q]  -49.3 108.05 180 top
J17  DELTA-L  [TRIANG_LAUNCH_3PXA]  -9.53 74.17 180 top
J18  DELTA-L  [TRIANG_LAUNCH_3PXA]  -9.52 29.84 0 top
J19  DELTA-L  [TRIANG_LAUNCH_3PXA]  -27.61 104.52 180 top
J20  DELTA-L  [TRIANG_LAUNCH_3PXA]  -27.6 29.84 0 top
J21  DELTA-L  [TRIANG_LAUNCH_3PXA]  -19.98 104.52 0 bottom
J22  DELTA-L  [TRIANG_LAUNCH_3PXA]  -19.99 29.84 180 bottom
J23  DELTA-L  [TRIANG_LAUNCH_3PXA]  -25.07 29.84 180 bottom
J24  DELTA-L  [TRIANG_LAUNCH_3PXA]  -25.06 104.52 0 bottom
J25  DELTA-L  [TRIANG_LAUNCH_3PXA]  -22.52 29.84 0 top
J26  DELTA-L  [TRIANG_LAUNCH_3PXA]  -22.53 104.52 180 top
J27  -  [TDR_3P_C85P67_141_100M_Q]  -56.51 108.05 0 bottom
J29  CONN2_210-HP1-02GBR05K  [HEADER1X2XJ_H339]  144.71 61.4 0 top
J30  CONN2_210-HP1-02GBR05K  [HEADER1X2XJ_H339]  141.45 61.4 0 top
L4  HCB2012KF-331T30  [L0805]  43.69 34.54 180 top
L5  BLM18PG121SN1D  [L0603]  118.75 40.01 180 bottom
L6  BLM15PX121SN1D  [L0402]  123.57 52.45 180 top
L7  BLM18KG121TN1D  [L0603]  118.36 35.2 180 bottom
L8  BLM18KG121TN1D  [L0603]  122.83 47.27 180 bottom
L9  BLM18KG121TN1D  [L0603]  125.1 44.85 90 bottom
ME1  -  [PCB_VENDOR_LOGO_15X8]  75.28 14.36 0 top
NOREF  -  []  115.8 1.94 0 top
NOREF#2  -  []  89.47 43.52 0 top
NOREF#3  -  []  24.86 47.63 0 top
NOREF#4  -  []  25.1 48.6 0 top
NOREF#5  -  []  78.43 24.49 90 top
NOREF#6  -  []  28.76 46.31 0 top
NOREF#7  -  []  5.21 56.88 0 top
NOREF#8  -  []  224.23 204.83 0 top
NOREF#9  -  []  30.51 25.13 90 top
NOREF#10  -  []  103.93 48.52 0 top
NOREF#11  -  []  68.9 46.9 0 top
NOREF#12  -  []  85.36 43.43 0 top
NOREF#13  -  []  75.86 47.63 0 top
NOREF#14  -  []  135.88 8.71 90 top
NOREF#15  -  []  3.04 20.18 0 top
NOREF#16  -  []  56.01 26.68 90 top
NOREF#17  -  []  78.43 22.78 0 top
NOREF#18  -  []  50.36 47.63 0 top
NOREF#19  -  []  -61 129.8 0 top
NOREF#20  -  [unnamed#2]  62.57 48.02 0 top
NOREF#21  -  []  68.97 1.94 0 top
NOREF#22  -  [unnamed#3]  164.88 129.8 0 top
NOREF#23  -  []  103.86 24.39 90 top
NOREF#24  -  []  143.89 18.43 0 top
NOREF#25  -  []  54.26 46.32 0 top
NOREF#26  -  []  46.1 19.23 0 top
NOREF#27  -  [unnamed#2]  114.34 53.38 0 top
NOREF#28  -  []  24.86 47.63 0 top
NOREF#29  -  []  27.36 48.61 0 top
NOREF#30  -  []  53.71 43.9 90 top
NOREF#31  -  []  38.08 6.07 0 top
NOREF#32  -  []  87.16 42.55 90 top
NOREF#33  -  []  28.76 46.31 0 top
NOREF#34  -  []  15.46 2.14 0 top
NOREF#35  -  []  27.44 24.48 90 top
NOREF#36  -  []  -1 45.42 90 top
NOREF#37  -  []  28.21 44.49 90 top
NOREF#38  -  []  121.42 44.5 0 top
NOREF#39  -  []  101.36 47.63 0 top
NOREF#40  -  []  91.4 19.23 0 top
NOREF#41  -  []  107.01 25.14 90 top
NOREF#42  -  []  7.69 21.18 0 top
NOREF#43  -  []  18.9 54.89 0 top
NOREF#44  -  []  50.34 5.63 0 top
NOREF#45  -  []  141.86 30.62 90 top
NOREF#46  -  []  3.46 51.86 0 top
NOREF#47  -  []  27.36 24.38 90 top
NOREF#48  -  []  36.05 1.94 0 top
NOREF#49  -  []  53.71 44.49 0 top
NOREF#50  -  []  18.97 26.06 90 top
NOREF#51  -  []  17.67 5.88 0 top
NOREF#52  -  []  79.21 44.49 90 top
NOREF#53  -  []  20.16 26.23 90 top
NOREF#54  -  []  0 0 0 top
NOREF#55  -  []  112.66 42.55 90 top
NOREF#56  -  []  87.4 43.52 0 top
NOREF#57  -  []  15.18 26.07 0 top
NOREF#58  -  []  103.86 48.62 0 top
NOREF#59  -  []  148.1 84.38 270 top
NOREF#60  -  []  101.6 48.6 0 top
NOREF#61  -  []  47.78 51.08 90 top
NOREF#62  -  []  -1 16.47 90 top
NOREF#63  -  []  61.66 42.55 90 top
NOREF#64  -  []  87.55 20.32 0 top
NOREF#65  -  []  36.16 42.55 90 top
NOREF#66  -  []  27.09 45.13 90 top
NOREF#67  -  []  79.21 43.9 90 top
NOREF#68  -  []  7.83 9.38 0 top
NOREF#69  -  []  77.95 49 0 top
NOREF#70  -  []  103.59 45.13 90 top
NOREF#71  -  []  112.66 42.55 0 top
NOREF#72  -  [unnamed#4]  164.88 0 0 top
NOREF#73  -  []  143.62 15.96 0 top
NOREF#74  -  []  78.43 15.78 0 top
NOREF#75  -  []  133.54 55.24 0 top
NOREF#76  -  []  79.76 46.32 0 top
NOREF#77  -  []  81.51 26.68 90 top
NOREF#78  -  []  142.68 64.9 0 top
NOREF#79  -  [unnamed#5]  -51 129.8 0 top
NOREF#80  -  []  -55.85 358.08 0 top
NOREF#81  -  []  53.71 44.49 90 top
NOREF#82  -  []  136.98 54.54 90 top
NOREF#83  -  []  43.58 54.43 0 top
NOREF#84  -  []  123.17 52.45 0 top
NOREF#85  -  []  -1 81.91 90 top
NOREF#86  -  []  36.16 42.55 0 top
NOREF#87  -  []  19.85 1.94 0 top
NOREF#88  -  []  141.86 35.7 0 top
NOREF#89  -  []  103.45 49 0 top
NOREF#90  -  []  48.56 48.51 0 top
NOREF#91  -  []  42.25 20.32 0 top
NOREF#92  -  []  79.76 46.32 0 top
NOREF#93  -  []  101.08 6.07 0 top
NOREF#94  -  []  46.1 19.23 0 top
NOREF#95  -  []  27.44 48.51 0 top
NOREF#96  -  []  142.9 50.76 0 top
NOREF#97  -  []  65.43 48.31 0 top
NOREF#98  -  []  142.9 50.76 0 top
NOREF#99  -  []  103.86 48.62 0 top
NOREF#100  -  []  0 0 0 top
NOREF#101  -  []  26.95 49 0 top
NOREF#102  -  []  76.1 48.6 0 top
NOREF#103  -  []  98.43 43.46 0 top
NOREF#104  -  []  148.1 16.17 90 top
NOREF#105  -  []  121.14 21.6 0 top
NOREF#106  -  []  63.97 43.52 0 top
NOREF#107  -  []  72.1 48.33 0 top
NOREF#108  -  []  78.43 48.52 0 top
NOREF#109  -  []  1.02 52.17 0 top
NOREF#110  -  []  105.26 46.32 90 top
NOREF#111  -  []  148.1 113.33 270 top
NOREF#112  -  []  95.18 42.56 0 top
NOREF#113  -  []  23.1 51.54 90 top
NOREF#114  -  []  114.97 43.52 0 top
NOREF#115  -  []  140.88 14.31 0 top
NOREF#116  -  []  28.21 43.89 90 top
NOREF#117  -  []  19.29 26.05 0 top
NOREF#118  -  []  104.71 43.9 90 top
NOREF#119  -  []  0 105.43 0 top
NOREF#120  -  []  52.45 49 0 top
NOREF#121  -  []  79.76 46.32 90 top
NOREF#122  -  []  133.53 54.54 0 top
NOREF#123  -  []  107.01 26.68 90 top
NOREF#124  -  []  104.71 44.49 90 top
NOREF#125  -  []  142.73 72.92 0 top
NOREF#126  -  []  121.42 43.7 90 top
NOREF#127  -  []  105.26 46.32 0 top
NOREF#128  -  []  52.93 48.52 0 top
NOREF#129  -  []  110.89 2.14 0 top
NOREF#130  -  []  72.24 36.52 0 top
NOREF#131  -  []  30.51 26.68 90 top
NOREF#132  -  []  104.71 44.49 0 top
NOREF#133  -  []  103.93 24.49 90 top
NOREF#134  -  []  4.49 19.76 0 top
NOREF#135  -  []  7.83 40.38 0 top
NOREF#136  -  []  81.51 25.14 90 top
NOREF#137  -  []  121.14 20.15 90 top
NOREF#138  -  []  112.66 42.55 0 top
NOREF#139  -  []  50.61 21.38 0 top
NOREF#140  -  []  0 63.9 0 top
NOREF#141  -  []  78.36 48.62 0 top
NOREF#142  -  []  141.98 37.02 0 top
NOREF#143  -  []  174.88 0 90 top
NOREF#144  -  []  54.26 46.32 90 top
NOREF#145  -  []  79.76 46.32 90 top
NOREF#146  -  []  78.09 45.13 90 top
NOREF#147  -  []  68.9 46.9 0 top
NOREF#148  -  []  95.91 21.38 0 top
NOREF#149  -  []  4.49 50.76 0 top
NOREF#150  -  []  16.05 26.24 90 top
NOREF#151  -  []  13.13 26.06 0 top
NOREF#152  -  []  136.97 55.24 90 top
NOREF#153  -  []  18.09 26.23 90 top
NOREF#154  -  []  79.21 44.49 0 top
NOREF#155  -  []  5 64.9 0 top
NOREF#156  -  []  52.59 45.13 90 top
NOREF#157  -  []  27.36 48.61 0 top
NOREF#158  -  []  61.9 43.52 0 top
NOREF#159  -  []  17.22 26.06 0 top
NOREF#160  -  []  78.36 48.62 0 top
NOREF#161  -  []  132 1.94 0 top
NOREF#162  -  []  112.9 43.52 0 top
NOREF#163  -  []  99.56 48.51 0 top
NOREF#164  -  []  50.6 48.6 0 top
NOREF#165  -  []  74.06 48.51 0 top
NOREF#166  -  []  14.01 26.24 90 top
NOREF#167  -  []  56.01 25.14 90 top
NOREF#168  -  []  144.41 50.71 0 top
NOREF#169  -  []  52.93 24.49 90 top
NOREF#170  -  []  4.49 50.76 0 top
NOREF#171  -  []  78.36 24.39 90 top
NOREF#172  -  []  136.97 55.24 90 top
NOREF#173  -  []  110.86 43.43 0 top
NOREF#174  -  []  21.04 26.05 90 top
NOREF#175  -  []  146.1 52.18 0 top
NOREF#176  -  []  89.76 19.07 0 top
NOREF#177  -  []  105.26 46.32 90 top
NOREF#178  -  []  7.69 52.18 0 top
NOREF#179  -  []  68.23 48.26 0 top
NOREF#180  -  []  285.5 16.94 0 top
NOREF#181  -  []  54.26 46.32 0 top
NOREF#182  -  []  44.46 19.07 0 top
NOREF#183  -  [unnamed#2]  23.91 35.75 0 top
NOREF#184  -  []  132.62 44.5 0 top
NOREF#185  -  []  28.76 46.31 90 top
NOREF#186  -  []  7.66 2.14 0 top
NOREF#187  -  []  34.36 43.43 0 top
NOREF#188  -  []  38.47 43.52 0 top
NOREF#189  -  []  141.98 29.3 90 top
NOREF#190  -  []  59.86 43.43 0 top
NOREF#191  -  []  120.87 45.05 0 top
NOREF#192  -  []  144.61 33.16 90 top
NOREF#193  -  []  140.88 14.31 0 top
NOREF#194  -  []  120.87 31.95 90 top
NOREF#195  -  []  -1 113.11 90 top
NOREF#196  -  []  148.1 50.42 90 top
NOREF#197  -  [unnamed#6]  -51 0 0 top
NOREF#198  -  []  78.43 15.78 90 top
NOREF#199  -  []  113.34 5.63 0 top
NOREF#200  -  []  121.42 32.5 90 top
NOREF#201  -  []  52.77 1.94 0 top
NOREF#202  -  []  95.18 40.76 90 top
NOREF#203  -  []  91.4 19.23 0 top
NOREF#204  -  []  4.49 19.76 0 top
NOREF#205  -  []  36.4 43.52 0 top
NOREF#206  -  []  47.86 2.14 0 top
NOREF#207  -  []  103.09 1.94 0 top
NOREF#208  -  []  28.21 44.49 0 top
NOREF#209  -  []  124.08 19.61 90 top
NOREF#210  -  []  61.66 42.55 0 top
NOREF#211  -  []  40.06 1.94 0 top
NOREF#212  -  []  28.76 46.31 90 top
NOREF#213  -  []  99.08 1.94 0 top
NOREF#214  -  []  23.06 48.51 0 top
NOREF#215  -  []  1.02 21.17 0 top
NOREF#216  -  []  18.9 53.09 90 top
NOREF#217  -  []  16.93 26.07 90 top
NOREF#218  -  []  82.88 1.94 0 top
NOREF#219  -  []  42.74 34.54 0 top
NOREF#220  -  []  43.58 52.63 90 top
NOREF#221  -  []  14.88 26.06 90 top
NOREF#222  -  []  105.26 46.32 0 top
NOREF#223  -  []  135.92 14.9 0 top
NOREF#224  -  []  147.1 0 90 top
NOREF#225  -  []  20.29 17.68 180 bottom
NOREF#226  -  [unnamed#2]  47 30.87 180 bottom
NOREF#227  -  [unnamed#2]  103.93 12.69 180 bottom
NOREF#228  -  [unnamed#2]  23.42 35.72 180 bottom
OSC1  25MHZ  [OSC4_FJ2500009]  121.67 54.61 270 top
PC72  1UF  [C0402-0201]  127.89 25.65 0 top
PR76  0  [R0402-0201]  123.32 27.69 270 bottom
Q1  BSS138BKS  [SOT363XB]  135.05 22.86 0 bottom
Q2  BSS138BKS  [SOT363XB]  115.31 17.87 270 top
Q3  2N7002KW  [SOT323XB]  2.24 26.8 270 top
Q4  2N7002KW  [SOT323XB]  4.96 26.78 270 top
Q5  SSM6N7002KFU  [SOT363_0-65_2X1-25XB]  21.23 52.68 270 bottom
Q6  SSM6N7002KFU  [SOT363_0-65_2X1-25XB]  44.91 51.61 270 bottom
Q7  SSM6N7002KFU  [SOT363_0-65_2X1-25XB]  71.98 58.04 90 bottom
Q8  SSM6N7002KFU  [SOT363_0-65_2X1-25XB]  95.05 52.55 180 bottom
Q9  SSM6N7002KFU  [SOT363_0-65_2X1-25XB]  8.99 36.6 0 top
Q10  SSM6N7002KFU  [SOT363_0-65_2X1-25XB]  48.69 42.11 270 bottom
Q11  SSM6N7002KFU  [SOT363_0-65_2X1-25XB]  60.34 19.53 90 top
Q12  SSM6N7002KFU  [SOT363_0-65_2X1-25XB]  88.93 28.04 90 bottom
R1  100  [R0402-0201]  17.73 12.57 270 top
R2  22  [R0402-0201]  10.41 12.57 270 top
R5  22  [R0402-0201]  13.16 12.57 270 top
R6  22  [R0402-0201]  11.33 12.57 90 bottom
R7  4.75K  [R0402-0201]  17.27 11.25 270 bottom
R8  22  [R0402-0201]  15.9 12.57 270 top
R9  22  [R0402-0201]  18.64 12.57 270 top
R10  22  [R0402-0201]  13.54 11.28 90 bottom
R11  5.36K  [R0402-0201]  14.55 11.28 90 bottom
R12  22  [R0402-0201]  23.21 14.86 90 bottom
R13  22  [R0402-0201]  24.22 14.86 90 bottom
R14  22  [R0402-0201]  25.73 12.45 270 top
R15  22  [R0402-0201]  26.62 12.45 270 top
R16  22  [R0402-0201]  26.67 11.94 180 bottom
R17  22  [R0402-0201]  30.61 12.83 0 bottom
R18  22  [R0402-0201]  53.34 10.72 180 top
R19  22  [R0402-0201]  53.34 10.72 0 bottom
R20  22  [R0402-0201]  26.92 10.92 0 bottom
R21  4.7K  [R0402-0201]  23.37 10.92 180 bottom
R22  4.7K  [R0402-0201]  25.15 10.92 180 bottom
R23  4.7K  [R0402-0201]  16.81 12.57 270 top
R24  4.7K  [R0402-0201]  19.56 12.57 270 top
R90  10K  [R0402-0201]  120.14 22.86 0 top
R169  750  [R0402-0201]  24 58.04 270 bottom
R170  200K  [R0402-0201]  23.55 60.53 0 top
R171  10K  [R0402-0201]  22.63 59.44 90 bottom
R172  750  [R0402-0201]  49.02 54.1 90 bottom
R173  200K  [R0402-0201]  38.02 57.48 90 top
R174  10K  [R0402-0201]  47.93 57.61 90 bottom
R175  26.7K  [R0402-0201]  23.93 61.93 90 top
R176  26.7K  [R0402-0201]  48.69 61.8 90 top
R177  750  [R0402-0201]  74.14 54.88 180 top
R178  200K  [R0402-0201]  63.55 56.36 90 top
R179  10K  [R0402-0201]  73.84 52.55 270 top
R180  750  [R0402-0201]  99.71 55.35 180 top
R181  200K  [R0402-0201]  99.31 60.58 0 top
R182  10K  [R0402-0201]  99.31 52.7 270 top
R183  26.7K  [R0402-0201]  74.22 61.82 90 top
R184  26.7K  [R0402-0201]  99.69 61.98 90 top
R185  4.7K  [R0402-0201]  128.4 27.69 90 bottom
R189  4.42K  [R0402-0201]  17.02 45.47 0 top
R190  120K  [R0402-0201]  11.43 45.72 0 top
R191  10K  [R0402-0201]  17.02 44.07 0 top
R192  4.42K  [R0402-0201]  45.92 43.18 0 top
R193  10K  [R0402-0201]  43.36 42.14 180 bottom
R194  120K  [R0402-0201]  40.46 43.23 90 top
R195  90.9K  [R0402-0201]  11.43 44.7 180 top
R196  90.9K  [R0402-0201]  43.36 43.33 0 bottom
R197  4.42K  [R0402-0201]  95.63 34.04 90 top
R198  4.42K  [R0402-0201]  68.81 27.38 180 top
R199  120K  [R0402-0201]  89.92 34.04 0 top
R200  10K  [R0402-0201]  96.01 32.51 0 top
R201  120K  [R0402-0201]  61.9 27.58 270 top
R202  10K  [R0402-0201]  68.94 26.19 0 top
R203  90.9K  [R0402-0201]  92.58 34.16 0 bottom
R204  90.9K  [R0402-0201]  60.91 27.58 90 top
R209  22  [R0402-0201]  138.43 30.48 180 bottom
R210  22  [R0402-0201]  138.43 31.5 180 bottom
R211  22  [R0402-0201]  138.43 30.48 180 top
R213  4.7K  [R0402-0201]  23.39 40.03 90 top
R214  4.7K  [R0402-0201]  24.89 40.03 270 top
R215  4.7K  [R0402-0201]  35.56 37.72 0 top
R216  4.7K  [R0402-0201]  35.59 39.17 0 top
R217  4.7K  [R0402-0201]  10.79 49.66 270 top
R218  4.7K  [R0402-0201]  10.67 53.59 90 top
R219  4.7K  [R0402-0201]  10.67 51.82 270 top
R220  0.01  [R1206XO_4P_SHORT]  23.1 53.24 90 top
R221  4.7K  [R0402-0201]  11.68 51.82 270 top
R222  22  [R0402-0201]  11.81 49.66 270 top
R223  4.7K  [R0402-0201]  11.68 53.59 90 top
R224  22  [R0402-0201]  17.78 46.86 180 top
R225  22  [R0402-0201]  14.22 47.37 180 top
R226  10  [R0402-0201]  19.15 52.73 180 top
R227  10  [R0402-0201]  19.15 51.74 180 top
R228  4.7K  [R0402-0201]  51.31 39.12 90 top
R229  4.7K  [R0402-0201]  50.04 39.12 90 top
R230  4.7K  [R0402-0201]  61.21 38.15 0 top
R231  4.7K  [R0402-0201]  61.21 39.17 0 top
R232  4.7K  [R0402-0201]  35.79 46.35 180 top
R233  4.7K  [R0402-0201]  42.98 51.69 0 top
R234  4.7K  [R0402-0201]  37.08 49.28 270 top
R235  0.01  [R1206XO_4P_SHORT]  47.78 52.78 90 top
R236  4.7K  [R0402-0201]  39.62 51.69 0 top
R237  4.7K  [R0402-0201]  38.1 49.66 270 top
R238  22  [R0402-0201]  37.59 47.5 270 top
R239  22  [R0402-0201]  40.89 45.52 90 top
R240  22  [R0402-0201]  39.75 45.47 90 top
R241  10  [R0402-0201]  45.09 50.8 180 top
R242  10  [R0402-0201]  45.09 49.76 180 top
R243  4.7K  [R0402-0201]  76.71 38.61 90 top
R244  4.7K  [R0402-0201]  75.31 38.73 270 top
R245  4.7K  [R0402-0201]  88.67 36.75 0 top
R246  4.7K  [R0402-0201]  89.03 38.23 270 top
R247  4.7K  [R0402-0201]  62.87 29.34 270 top
R248  4.7K  [R0402-0201]  63.63 35.05 90 top
R249  4.7K  [R0402-0201]  61.98 32.77 270 top
R250  0.01  [R1206XO_4P_SHORT]  72.9 34.37 90 top
R251  22  [R0402-0201]  63.88 29.34 270 top
R252  4.7K  [R0402-0201]  63.37 33.66 180 top
R253  4.7K  [R0402-0201]  63.37 32.38 0 top
R254  49.9  [R0402-0201]  67.26 28.75 180 top
R255  22  [R0402-0201]  65.48 28.75 180 top
R256  10  [R0402-0201]  70.69 34.14 180 top
R257  10  [R0402-0201]  70.69 33.1 180 top
R258  4.7K  [R0402-0201]  101.98 38.86 90 top
R259  4.7K  [R0402-0201]  98.55 35.69 0 top
R260  4.7K  [R0402-0201]  111.66 35.56 90 top
R261  4.7K  [R0402-0201]  111.66 37.34 270 top
R262  4.7K  [R0402-0201]  90.42 37.34 270 top
R263  4.7K  [R0402-0201]  93.47 45.47 0 top
R264  4.7K  [R0402-0201]  91.44 44.96 180 top
R265  0.01  [R1206XO_4P_SHORT]  100.13 43.46 180 top
R266  4.7K  [R0402-0201]  93.47 44.45 0 top
R267  4.7K  [R0402-0201]  91.44 43.94 180 top
R268  22  [R0402-0201]  91.44 37.34 270 top
R269  22  [R0402-0201]  95.25 36.83 180 top
R270  22  [R0402-0201]  95.25 35.81 180 top
R271  10  [R0402-0201]  98.35 41.76 180 top
R272  10  [R0402-0201]  98.35 40.79 180 top
R273  10K  [R0402-0201]  125.73 61.34 270 bottom
R274  10K  [R0402-0201]  125.73 59.31 90 bottom
R275  10K  [R0402-0201]  125.73 57.53 270 bottom
R276  0  [R0402-0201]  117.73 58.29 90 top
R277  22  [R0402-0201]  119.51 60.45 0 top
R278  22  [R0402-0201]  118.24 62.41 0 top
R279  220  [R0402-0201]  126.75 61.34 90 bottom
R280  220  [R0402-0201]  126.75 59.31 270 bottom
R281  220  [R0402-0201]  126.75 57.53 90 bottom
R282  4.7K  [R0402-0201]  136.14 41.66 0 top
R283  4.7K  [R0402-0201]  136.91 52.58 90 top
R284  4.7K  [R0402-0201]  137.92 52.58 270 top
R285  4.7K  [R0402-0201]  136.14 40.64 180 top
R286  10K  [R0402-0201]  90.68 49.91 180 bottom
R287  10K  [R0402-0201]  90.68 48.77 180 bottom
R288  10K  [R0402-0201]  88.77 46.99 90 top
R289  22  [R0402-0201]  94.87 47.62 180 bottom
R290  75  [R0402-0201]  94.87 48.77 180 bottom
R291  22  [R0402-0201]  95.68 49.91 180 bottom
R292  220  [R0402-0201]  90.68 51.05 0 bottom
R293  220  [R0402-0201]  90.68 47.62 0 bottom
R294  220  [R0402-0201]  87.68 46.99 270 top
R295  4.7K  [R0402-0201]  92.58 49.91 180 bottom
R296  3.3K  [R0402-0201]  145.21 18.95 180 bottom
R297  3.65K  [R0402-0201]  145.16 29.13 180 bottom
R298  1K  [R0402-0201]  138.86 26.14 180 bottom
R305  120K  [R0402-0201]  121.18 14.81 270 top
R306  2K  [R0402-0201]  119.3 19.58 180 top
R307  10K  [R0402-0201]  120.4 20.85 180 top
R308  90.9K  [R0402-0201]  119.84 15.19 180 top
R309  33  [R0402-0201]  121.79 21.23 90 top
R319  10K  [R0402-0201]  121.16 52.07 270 top
R400  22  [R0402-0201]  134.26 26.37 270 bottom
R401  22  [R0402-0201]  137.01 26.37 270 bottom
R402  22  [R0402-0201]  138.43 35.56 0 top
R410  4.7K  [R0402-0201]  134.34 24.92 0 bottom
R411  4.7K  [R0402-0201]  136.65 24.93 180 bottom
R412  4.7K  [R0402-0201]  112.86 16.89 180 top
R413  10K  [R0402-0201]  112.9 15.75 0 top
R414  4.7K  [R0402-0201]  119.84 58.93 270 top
R417  220  [R0402-0201]  118.87 58.93 270 top
R418  33.2  [R0402-0201]  30.48 41.15 90 bottom
R419  33.2  [R0402-0201]  29.34 41.15 90 bottom
R420  33.2  [R0402-0201]  55.5 41.66 180 bottom
R421  33.2  [R0402-0201]  55.5 40.39 180 bottom
R422  200  [R0402-0201]  81.28 40.39 180 bottom
R423  33.2  [R0402-0201]  81.28 38.99 180 bottom
R424  33.2  [R0402-0201]  105.08 42.29 180 bottom
R425  33.2  [R0402-0201]  105.08 40.77 180 bottom
R426  10  [R0402-0201]  132.13 19.53 270 bottom
R427  10  [R0402-0201]  133.12 19.53 270 bottom
R428  10  [R0402-0201]  112.9 18.03 180 top
R429  10  [R0402-0201]  115.08 15.08 270 top
R433  100  [R0402-0201]  138.43 34.54 0 top
R438  9.09K  [R0402-0201]  13.64 60.91 180 top
R439  200K  [R0402-0201]  13.26 58.5 90 top
R440  9.76K  [R0402-0201]  14.27 58.5 270 top
R441  20.5K  [R0402-0201]  13.89 56.85 180 top
R442  200K  [R0402-0201]  48.31 60.4 0 top
R443  9.76K  [R0402-0201]  39.04 57.48 270 top
R444  9.09K  [R0402-0201]  38.4 59.89 180 top
R445  20.5K  [R0402-0201]  38.66 56.08 180 top
R446  200K  [R0402-0201]  73.84 60.43 0 top
R447  9.76K  [R0402-0201]  64.57 56.36 270 top
R448  9.09K  [R0402-0201]  63.93 58.78 180 top
R449  20.5K  [R0402-0201]  64.19 54.97 180 top
R450  200K  [R0402-0201]  89.03 56.52 90 top
R451  9.76K  [R0402-0201]  90.04 56.52 270 top
R452  9.09K  [R0402-0201]  89.41 58.93 180 top
R453  20.5K  [R0402-0201]  89.66 55.12 180 top
R454  200K  [R0402-0201]  10.87 46.2 0 bottom
R455  1.69K  [R0402-0201]  9.27 38.61 0 top
R456  200K  [R0402-0201]  41.96 42.44 90 bottom
R457  1.69K  [R0402-0201]  43.13 35.1 270 bottom
R458  200K  [R0402-0201]  66.7 21.49 0 bottom
R459  1.69K  [R0402-0201]  64.87 20.24 0 bottom
R460  200K  [R0402-0201]  95.4 24.84 0 top
R461  1.69K  [R0402-0201]  91.57 24.36 0 top
R462  200K  [R0402-0201]  132.51 17.91 180 top
R463  3.65K  [R0402-0201]  132.51 15.88 0 top
R464  1K  [R0402-0201]  13.64 61.93 180 top
R465  1K  [R0402-0201]  38.4 60.91 180 top
R466  1K  [R0402-0201]  63.93 59.79 180 top
R467  1K  [R0402-0201]  89.41 59.94 180 top
R473  28K  [R0402-0201]  132.51 18.92 0 top
R474  110K  [R0402-0201]  132.51 19.94 0 top
R475  1K  [R0402-0201]  132.51 14.86 0 top
R476  10K  [R0402-0201]  37.72 32.26 270 top
R477  10K  [R0402-0201]  36.7 32.26 90 top
R478  10K  [R0402-0201]  37.34 29.08 270 bottom
R479  10K  [R0402-0201]  37.72 27.69 0 bottom
R480  10K  [R0402-0201]  39.04 31.91 180 bottom
R481  10K  [R0402-0201]  35.69 32.26 90 top
R490  1K  [R0402-0201]  11.05 38.61 180 top
R491  28K  [R0402-0201]  16.89 39.24 90 top
R492  110K  [R0402-0201]  17.88 39.24 270 top
R493  22  [R0402-0201]  36.58 23.11 90 top
R494  22  [R0402-0201]  117.51 60.23 90 top
R495  28K  [R0402-0201]  45.75 37.11 0 bottom
R496  1K  [R0402-0201]  41.76 35.28 180 bottom
R497  110K  [R0402-0201]  43.99 37.11 180 bottom
R498  28K  [R0402-0201]  68.48 21.49 0 bottom
R499  110K  [R0402-0201]  68.71 20.42 0 bottom
R500  1K  [R0402-0201]  63.37 19.23 180 bottom
R501  28K  [R0402-0201]  95.66 23.83 0 top
R502  110K  [R0402-0201]  96.19 26.29 90 top
R503  1K  [R0402-0201]  89.79 24.36 180 top
R504  1  [R0603_H24]  39.12 35.31 180 top
R505  4.7K  [R0402-0201]  136.14 43.69 180 top
R506  4.7K  [R0402-0201]  136.14 42.67 0 top
R507  200K  [R0402-0201]  10.26 29.61 90 bottom
R508  9.76K  [R0402-0201]  9.28 29.61 90 bottom
R509  20K  [R0402-0201]  8.31 29.61 270 bottom
R510  28K  [R0402-0201]  11.23 29.26 90 bottom
R511  1K  [R0402-0201]  12.54 28.59 270 bottom
R512  51K  [R0402-0201]  130.43 29.72 90 bottom
R513  51K  [R0402-0201]  5.26 25.6 0 bottom
R514  22  [R0402-0201]  6.06 26.53 0 bottom
R518  4.7K  [R0402-0201]  130.56 50.04 270 bottom
R519  4.7K  [R0402-0201]  130.56 47.37 90 bottom
R520  10K  [R0402-0201]  20.39 34.56 0 top
R521  15.8K  [R0402-0201]  20.44 32.08 0 top
R522  28K  [R0402-0201]  21.18 28.46 180 top
R523  200K  [R0402-0201]  21.2 27.49 0 top
R524  100  [R0402-0201]  16.35 35.97 0 top
R525  71.5K  [R0402-0201]  14.98 36.36 90 top
R526  10K  [R0402-0201]  19.3 36.58 180 top
R527  4.7K  [R0402-0201]  136.65 50.04 270 top
R528  4.7K  [R0402-0201]  136.65 47.37 90 top
R529  10K  [R0402-0201]  8.3 24.83 180 top
R530  0  [R0402-0201]  1.95 24.57 0 top
R531  0  [R0402-0201]  5.59 24.64 0 top
R532  4.7K  [R0402-0201]  134.87 52.58 270 top
R533  4.7K  [R0402-0201]  135.89 52.58 90 top
R534  0  [R1206XI]  18.09 27.68 90 bottom
R535  0  [R1206XI]  16.05 27.69 90 bottom
R536  0  [R1206XI]  14.01 27.69 90 bottom
R537  0  [R1206XI]  20.16 27.68 90 bottom
R538  10  [R0603_H24]  11.67 25.37 90 bottom
R539  22  [R0402-0201]  124.33 27.69 270 top
R540  22  [R0402-0201]  120.27 27.69 270 top
R541  22  [R0402-0201]  121.28 27.69 270 top
R542  22  [R0402-0201]  123.32 27.69 270 top
R544  22  [R0402-0201]  126.36 27.69 270 top
R545  22  [R0402-0201]  125.35 27.69 270 top
R548  22  [R0402-0201]  118.87 33.02 0 top
R550  22  [R0402-0201]  117.22 27.56 90 bottom
R551  22  [R0402-0201]  128.4 29.72 270 top
R552  22  [R0402-0201]  128.4 29.72 90 bottom
R553  22  [R0402-0201]  128.4 27.69 270 top
R554  22  [R0402-0201]  129.41 29.72 270 top
R555  22  [R0402-0201]  130.43 27.69 270 top
R556  22  [R0402-0201]  131.44 27.69 270 top
R557  22  [R0402-0201]  133.48 27.69 270 top
R559  0  [R0402-0201]  118.87 41.78 0 bottom
R560  0  [R0402-0201]  118.87 42.8 0 bottom
R561  22  [R0402-0201]  116.84 32 0 top
R562  49.9K  [R0402-0201]  118.87 41.02 180 top
R563  22  [R0402-0201]  114.55 33.02 0 top
R564  49.9K  [R0402-0201]  118.87 40.01 180 top
R565  4.7K  [R0402-0201]  123.32 29.72 90 top
R566  4.7K  [R0402-0201]  126.36 29.72 90 top
R567  4.7K  [R0402-0201]  124.33 29.72 90 top
R568  4.7K  [R0402-0201]  125.35 29.72 90 top
R569  4.7K  [R0402-0201]  120.27 29.72 90 top
R570  4.7K  [R0402-0201]  121.28 29.72 90 top
R571  4.7K  [R0402-0201]  130.43 29.72 90 top
R572  4.7K  [R0402-0201]  131.44 29.72 90 top
R573  4.7K  [R0402-0201]  133.48 29.72 90 top
R574  4.7K  [R0402-0201]  118.24 27.56 90 bottom
R575  4.7K  [R0402-0201]  118.24 27.64 90 top
R576  4.7K  [R0402-0201]  118.87 32 0 top
R577  10K  [R0402-0201]  134.62 52.58 90 bottom
R578  1K  [R0402-0201]  122.17 50.04 90 top
R579  332  [R0402-0201]  121.16 47.37 270 top
R584  22  [R0402-0201]  138.43 28.45 180 bottom
R586  22  [R0402-0201]  138.43 29.46 180 bottom
R590  0  [R0402-0201]  138.43 36.58 180 top
R591  22  [R0402-0201]  136.14 36.58 180 top
R596  1K  [R0402-0201]  132.59 47.37 270 top
R598  4.7K  [R0402-0201]  136.14 30.48 180 top
R599  4.7K  [R0402-0201]  136.14 31.5 180 top
R600  4.7K  [R0402-0201]  136.14 32.51 180 top
R602  4.7K  [R0402-0201]  136.14 33.53 180 top
R604  4.7K  [R0402-0201]  136.14 33.53 180 bottom
R605  4.7K  [R0402-0201]  136.14 30.48 180 bottom
R607  4.7K  [R0402-0201]  136.14 32.51 180 bottom
R608  4.7K  [R0402-0201]  136.14 31.5 180 bottom
R611  4.7K  [R0402-0201]  136.14 28.45 180 bottom
R613  4.7K  [R0402-0201]  136.14 29.46 180 bottom
R617  100K  [R0402-0201]  121.13 45.69 0 bottom
R619  100K  [R0402-0201]  122.17 47.37 270 top
R620  22  [R0402-0201]  136.14 39.62 180 top
R621  22  [R0402-0201]  136.65 50.04 270 bottom
R622  22  [R0402-0201]  134.62 47.37 270 bottom
R623  22  [R0402-0201]  136.14 38.61 180 top
R624  22  [R0402-0201]  136.65 38.27 90 bottom
R625  22  [R0402-0201]  136.14 37.59 180 top
R626  22  [R0402-0201]  133.69 40.9 180 bottom
R627  4.7K  [R0402-0201]  126.36 50.04 270 bottom
R628  4.7K  [R0402-0201]  125.22 50.04 90 bottom
R629  4.7K  [R0402-0201]  122.69 49.98 270 bottom
R630  22  [R0402-0201]  129.54 50.04 90 top
R631  22  [R0402-0201]  130.56 50.04 90 top
R632  22  [R0402-0201]  127.51 50.04 90 top
R633  22  [R0402-0201]  127.51 47.37 90 bottom
R634  22  [R0402-0201]  126.36 47.37 90 top
R635  4.7K  [R0402-0201]  125.22 50.04 90 top
R636  4.7K  [R0402-0201]  125.22 47.37 270 top
R639  4.7K  [R0402-0201]  129.54 47.37 270 top
R640  4.7K  [R0402-0201]  130.56 47.37 270 top
R641  4.7K  [R0402-0201]  127.51 47.37 270 top
R646  1K  [R0402-0201]  144.56 56.64 180 top
R651  10K  [R0402-0201]  144.56 55.68 0 top
R659  0  [R0603]  127.89 53.98 90 top
R660  22  [R0402-0201]  120.02 52.07 270 top
R661  0.51  [R0402-0201]  124.21 54.74 90 top
R663  10.2K  [R0402-0201]  117.35 23.88 180 top
R664  5.11K  [R0402-0201]  121.59 24.31 270 top
R665  22  [R0402-0201]  138.43 31.5 180 top
R666  22  [R0402-0201]  138.43 32.51 180 top
R667  22  [R0402-0201]  138.43 33.53 180 top
R674  22  [R0402-0201]  131.57 47.37 270 top
R675  47K  [R0402-0201]  132.46 50.04 270 top
R679  22  [R0402-0201]  139.82 38.31 270 top
R680  22  [R0402-0201]  136.14 34.54 0 top
R681  22  [R0402-0201]  136.14 35.56 0 top
R685  22  [R0402-0201]  126.36 47.37 90 bottom
R690  22  [R0402-0201]  134.62 50.04 90 top
R691  0  [R0402-0201]  134.62 47.37 90 top
R694  22  [R0402-0201]  132.46 27.69 270 top
R695  22  [R0402-0201]  117.22 27.64 90 top
R696  4.7K  [R0402-0201]  116.84 33.02 180 top
R697  4.7K  [R0402-0201]  132.46 29.72 90 top
R698  22  [R0402-0201]  122.3 27.69 270 top
R699  4.7K  [R0402-0201]  122.3 29.72 90 top
R700  22  [R0402-0201]  118.87 35.05 180 top
R701  4.7K  [R0402-0201]  118.87 34.04 0 top
R707  4.7K  [R0402-0201]  119.25 27.69 90 bottom
R708  4.7K  [R0402-0201]  118.24 29.72 90 bottom
R709  22  [R0402-0201]  138.43 33.53 180 bottom
R710  22  [R0402-0201]  138.43 32.51 180 bottom
R711  22  [R0402-0201]  138.43 34.54 180 bottom
R712  22  [R0402-0201]  138.43 35.56 180 bottom
R713  4.7K  [R0402-0201]  136.14 34.54 180 bottom
R714  4.7K  [R0402-0201]  136.14 35.56 180 bottom
R723  22  [R0402-0201]  119.25 29.72 90 bottom
R724  22  [R0402-0201]  128.52 50.04 90 top
R725  22  [R0402-0201]  129.41 27.69 270 top
R726  22  [R0402-0201]  138.43 38.61 180 top
R727  22  [R0402-0201]  116.84 33.02 0 bottom
